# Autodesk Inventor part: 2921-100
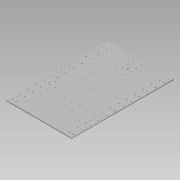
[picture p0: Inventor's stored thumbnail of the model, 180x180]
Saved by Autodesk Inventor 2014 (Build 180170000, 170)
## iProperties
Company: NHTSA/VRTC
Created: 2012-08
Part Number: 2921-100
Material: Steel
Document SubType Name: Modeling
Designer: Mike Vanvoorhis
Density: 7.85 g/cm^3
Mass: 229155 g
Surface Area: 47362.1 cm^2
Volume: 29191.7 cm^3
Project: CHILD SIDE IMPACT SLED
Description: BASE PLATE
Appearance: Steel
Author: Dave Walker
Title: Plate, Base
Subject: Child Side Impact Sled
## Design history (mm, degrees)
sketch "Sketch1"
  geometry: L1 (0, 0)-(1219.2, 0); L2 (1219.2, 0)-(1219.2, 12.7); L3 (1219.2, 12.7)-(0, 12.7); L4 (0, 12.7)-(0, 0)
  constraints: 8 end point, 2 parallel, 1 horizontal, 1 perpendicular
  dimensions: "d0" = 1219.2 distance of L3.end L2.end; "d1" = 12.7 distance of L3.end L1.start
extrude "Extrusion1" new body sketch "Sketch1" distance "d2" = 1898.65; taper "d3" = 0 deg
sketch "Sketch2"
  geometry: L1 (1219.2, 1898.65)-(0, 1898.65) reference; L2 (1219.2, 0)-(0, 0) reference; L3 (609.6, 1898.65)-(609.6, 0); C1 r 7.937 at (38.1, 76.2); C2 r 7.938 at (38.1, 228.6); C3 r 7.938 at (38.1, 381); C4 r 7.937 at (38.1, 533.4); C5 r 7.937 at (38.1, 685.8); C6 r 7.937 at (38.1, 838.2); C7 r 7.937 at (38.1, 990.6); C8 r 7.938 at (38.1, 1143); C9 r 7.938 at (38.1, 1295.4); C10 r 7.938 at (38.1, 1447.8); C11 r 7.937 at (38.1, 1600.2); C12 r 7.938 at (38.1, 1752.6); C13 r 7.938 at (114.3, 76.2); C14 r 7.937 at (114.3, 1752.6); C15 r 7.937 at (114.3, 1600.2); C16 r 7.937 at (114.3, 1447.8); C17 r 7.937 at (114.3, 1295.4); C18 r 7.938 at (114.3, 1143); C19 r 7.938 at (114.3, 990.6); C20 r 7.937 at (114.3, 838.2); C21 r 7.937 at (114.3, 685.8); C22 r 7.937 at (114.3, 533.4); C23 r 7.937 at (114.3, 381); C24 r 7.938 at (114.3, 228.6); C25 r 7.937 at (1104.9, 381); C26 r 7.938 at (1181.1, 381); C27 r 7.938 at (1181.1, 228.6); C28 r 7.938 at (1104.9, 228.6); C29 r 7.938 at (1104.9, 76.2); C30 r 7.937 at (1181.1, 76.2); C31 r 7.937 at (1181.1, 533.4); C32 r 7.937 at (1104.9, 533.4); C33 r 7.937 at (1104.9, 685.8); C34 r 7.937 at (1181.1, 685.8); C35 r 7.937 at (1181.1, 838.2); C36 r 7.937 at (1104.9, 838.2); C37 r 7.937 at (1181.1, 990.6); C38 r 7.938 at (1104.9, 990.6); C39 r 7.938 at (1181.1, 1143); C40 r 7.938 at (1104.9, 1143); C41 r 7.937 at (1104.9, 1295.4); C42 r 7.938 at (1181.1, 1295.4); C43 r 7.938 at (1181.1, 1447.8); C44 r 7.937 at (1104.9, 1447.8); C45 r 7.937 at (1181.1, 1600.2); C46 r 7.937 at (1104.9, 1600.2); C47 r 7.938 at (1181.1, 1752.6); C48 r 7.937 at (1104.9, 1752.6)
  constraints: 48 centre point, 24 symmetric about line, 2 end point, 2 midpoint, 24 other
hole "Hole1" sketch "Sketch2" diameter "d57" = 17.4625; stored, may be unused: countersink angle "d61" = 82 deg, drill point angle "d63" = 118 deg; dims "d58" = 19.05, "d59" = 9.525, "d60" = 6.35, "d62" = 25.4
sketch "Sketch4"
  geometry: L1 (1219.2, 1898.65)-(0, 1898.65) reference; L2 (0, 0)-(0, 1898.65) reference; L3 (0, 1878.584)-(368.3, 1878.584); L4 (368.3, 1878.584)-(491.3, 1878.584); L5 (891.3, 1878.584)-(768.3, 1878.584); L6 (1219.2, 0)-(0, 0) reference; L7 (368.3, 1878.584)-(368.3, 1718.564); L8 (368.3, 1718.564)-(491.3, 1718.564); L9 (491.3, 1718.564)-(491.3, 1558.544); L10 (491.3, 1558.544)-(368.3, 1558.544); L11 (368.3, 1558.544)-(368.3, 1398.778); L12 (368.3, 1398.778)-(491.3, 1398.778); L13 (491.3, 1398.778)-(491.3, 1238.758); L14 (491.3, 1238.758)-(368.3, 1238.758); L15 (368.3, 1238.758)-(368.3, 1078.738); L16 (368.3, 1078.738)-(491.3, 1078.738); L17 (491.3, 1078.738)-(491.3, 918.718); L18 (491.3, 918.718)-(368.3, 918.718); L19 (368.3, 918.718)-(368.3, 758.698); L20 (368.3, 758.698)-(491.3, 758.698); L21 (768.3, 1878.584)-(768.3, 1718.564); L22 (768.3, 1718.564)-(891.3, 1718.564); L23 (891.3, 1718.564)-(891.3, 1558.544); L24 (891.3, 1558.544)-(768.3, 1558.544); L25 (768.3, 1558.544)-(768.3, 1398.778); L26 (768.3, 1398.778)-(891.3, 1398.778); L27 (891.3, 1398.778)-(891.3, 1238.758); L28 (891.3, 1238.758)-(768.3, 1238.758); L29 (768.3, 1238.758)-(768.3, 1078.738); L30 (768.3, 1078.738)-(891.3, 1078.738); L31 (891.3, 1078.738)-(891.3, 918.718); L32 (891.3, 918.718)-(768.3, 918.718); L33 (768.3, 918.718)-(768.3, 758.698); L34 (768.3, 758.698)-(891.3, 758.698); L35 (491.3, 758.698)-(491.3, 598.678); L36 (491.3, 598.678)-(368.3, 598.678); L37 (891.3, 758.698)-(891.3, 598.678); L38 (891.3, 598.678)-(768.3, 598.678); L39 (0, 0)-(0, 666.496)
  constraints: 72 end point, 25 collinear, 16 parallel, 15 perpendicular, 5 point on line, 1 vertical alignment
  dimensions: "d73" = 368.3 distance of L3.start L3.end; "d74" = 20.066 distance of L1.end L3.start; "d280" = 180.086 distance from line of L7.end L1; "d284" = 340.106 distance between parallel lines of L10 L1; "d285" = 499.872 distance between parallel lines of L12 L1; "d286" = 659.892 distance between parallel lines of L14 L1; "d287" = 819.912 distance between parallel lines of L16 L1; "d288" = 979.932 distance between parallel lines of L18 L1; "d289" = 1139.952 distance between parallel lines of L20 L1; "d290" = 1299.972 distance between parallel lines of L36 L1; "d291" = 123 distance of L4.end L3.end; "d292" = 123 distance of L5.start L5.end (derived); "d293" = 277 distance of L5.end L4.end
hole "Hole3" sketch "Sketch4" diameter "d78" = 8.382; stored, may be unused: countersink angle "d82" = 82 deg, drill point angle "d84" = 118 deg; dims "d79" = 19.05, "d80" = 9.525, "d81" = 6.35, "d83" = 25.4
sketch "Sketch6"
  geometry: L1 (1219.2, 1898.65)-(0, 1898.65) reference; L2 (0, 0)-(0, 1898.65) reference; L3 (1219.2, 0)-(1219.2, 1898.65) reference; L4 (0, 1816.1)-(552.45, 1816.1); L5 (552.45, 1898.65)-(552.45, 1816.1)
  constraints: 4 end point, 2 perpendicular, 2 point on line
  dimensions: "d120" = 552.45 distance of L4.start L4.end; "d121" = 82.55 distance of L5.start L4.end
hole "Hole4" sketch "Sketch6" at (552.45, 1816.1) diameter "d122" = 17.4625; stored, may be unused: countersink angle "d126" = 82 deg, drill point angle "d128" = 118 deg; dims "d123" = 19.05, "d124" = 9.525, "d125" = 6.35, "d127" = 25.4
sketch "Sketch7"
  geometry: L1 (1219.2, 0)-(1219.2, 1898.65) reference; L2 (552.45, 1816.1)-(702.564, 1816.1); L3 (702.564, 1816.1)-(702.564, 1714.5); L4 (702.564, 1714.5)-(552.45, 1714.5); L5 (552.45, 1714.5)-(552.45, 1612.9); L6 (552.45, 1612.9)-(702.564, 1612.9); L7 (702.564, 1612.9)-(702.564, 1511.3); L8 (702.564, 1511.3)-(552.45, 1511.3); C1 r 8.731 at (552.45, 1816.1) reference
  constraints: 14 end point, 5 equal length, 2 perpendicular
  dimensions: "d129" = 150.114 distance of L2.start L2.end; "d130" = 101.6 distance of L2.end L3.end; "d131" = 150.114 distance of L3.end L4.end (derived); "d132" = 101.6 distance of L4.end L5.end; "d133" = 150.114 distance of L5.end L6.end (derived); "d134" = 101.6 distance of L6.end L7.end; "d135" = 150.114 distance of L7.end L8.end (derived)
hole "Hole5" sketch "Sketch7" at (702.564, 1816.1), (702.564, 1714.5), (552.45, 1714.5), (552.45, 1612.9), (702.564, 1612.9), (702.564, 1511.3), (552.45, 1511.3) diameter "d136" = 17.4625; stored, may be unused: countersink angle "d140" = 82 deg, drill point angle "d142" = 118 deg; dims "d137" = 19.05, "d138" = 9.525, "d139" = 6.35, "d141" = 25.4
sketch "Sketch12"
  geometry: L1 (637.032, 1619.25)-(637.032, 1641.475); L2 (617.982, 1641.475)-(617.982, 1619.25); L3 (1219.2, 1898.65)-(0, 1898.65) reference; C1 r 8.731 at (702.564, 1816.1) reference; C2 r 8.731 at (552.45, 1816.1) reference; A1 r 9.525 centre (627.507, 1641.475) between (637.032, 1641.475) and (617.982, 1641.475); A2 r 9.485 centre (627.507, 1631.083) between (635.723, 1626.343) and (635.723, 1626.343); A3 r 9.525 centre (627.507, 1619.25) between (617.982, 1619.25) and (637.032, 1619.25)
  constraints: 6 point on circle, 4 end point, 4 tangent, 3 centre point, 1 parallel, 1 vertical alignment
  dimensions: "d242" = 9.525 radius of A1; "d244" = 22.225 distance of A3.centre A1.centre; "d245" = 257.175 distance from line of L3 A1.centre; "d249" = 150.114 distance of C1.centre C2.centre (derived); "d294" = 75.057 horizontal distance of A1.centre C2.centre
extrude "Extrusion2" cut sketch "Sketch12" distance "d240" = 12.7; taper "d241" = 0 deg
sketch "Sketch13"
  geometry: C1 r 6.747 at (206.375, 21.59) reference; C2 r 6.747 at (403.225, 21.59) reference; C3 r 6.747 at (571.5, 21.59) reference; C4 r 6.747 at (800.1, 154.94) reference; C5 r 6.747 at (800.1, 554.99) reference; C6 r 6.747 at (651.669, 554.99) reference; C7 r 6.747 at (503.238, 554.99) reference; C8 r 6.747 at (354.806, 554.99) reference; C9 r 6.747 at (206.375, 554.99) reference; C10 r 6.747 at (206.375, 421.64) reference; C11 r 6.747 at (206.375, 288.29) reference; C12 r 6.747 at (206.375, 154.94) reference; C13 r 6.74 at (158.7, 657.09) reference; C14 r 6.74 at (158.7, 758.79) reference; C15 r 6.74 at (260.4, 758.79) reference; C16 r 6.74 at (260.4, 657.09) reference; C17 r 6.74 at (1002.3, 356.59) reference; C18 r 6.74 at (1104, 356.59) reference; C19 r 6.74 at (1104, 458.29) reference; C20 r 6.74 at (1002.3, 458.29) reference; C21 r 6.744 at (800.1, 421.64) reference; 22 further points
  constraints: 21 centre point, 19 coincident, 11 horizontal alignment, 10 vertical alignment, 42 other
hole "Hole8" sketch "Sketch13" diameter "d273" = 10.1092; stored, may be unused: countersink angle "d277" = 82 deg, drill point angle "d279" = 118 deg; dims "d274" = 19.05, "d275" = 9.525, "d276" = 6.35, "d278" = 25.4
body "Solid1"
